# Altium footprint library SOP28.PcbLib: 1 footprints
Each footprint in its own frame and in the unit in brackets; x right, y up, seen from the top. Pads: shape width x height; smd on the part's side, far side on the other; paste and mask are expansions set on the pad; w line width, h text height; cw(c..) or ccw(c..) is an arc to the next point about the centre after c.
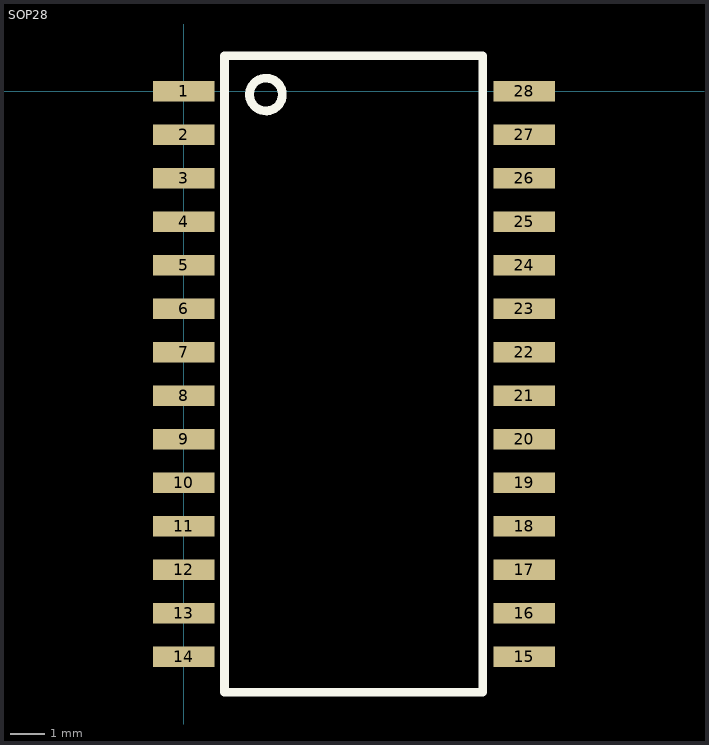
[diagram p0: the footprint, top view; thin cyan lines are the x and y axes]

## SOP28 [mm]
pads (28):
  rect 1.8x0.6 smd: 1(0,0) 2(0,-1.27) 3(0,-2.54) 4(0,-3.81) 5(0,-5.08) 6(0,-6.35) 7(0,-7.62) 8(0,-8.89) 9(0,-10.16) 10(0,-11.43) 11(0,-12.7) 12(0,-13.97) 13(0,-15.24) 14(0,-16.51) 15(9.94,-16.51) 16(9.94,-15.24) 17(9.94,-13.97) 18(9.94,-12.7) 19(9.94,-11.43) 20(9.94,-10.16) 21(9.94,-8.89) 22(9.94,-7.62) 23(9.94,-6.35) 24(9.94,-5.08) 25(9.94,-3.81) 26(9.94,-2.54) 27(9.94,-1.27) 28(9.94,0)
Top Overlay:
  circle w0.254: c2.4,-0.1 r0.479
  lines w0.254: 1.19,-17.54 8.73,-17.54 8.73,1.03 1.19,1.03 1.19,-17.52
